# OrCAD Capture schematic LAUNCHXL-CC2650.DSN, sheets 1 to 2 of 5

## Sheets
1 5_Mech: size A3; title: LAUNCHXL-CC2650; rev: 1.3.0; company: Texas Instruments
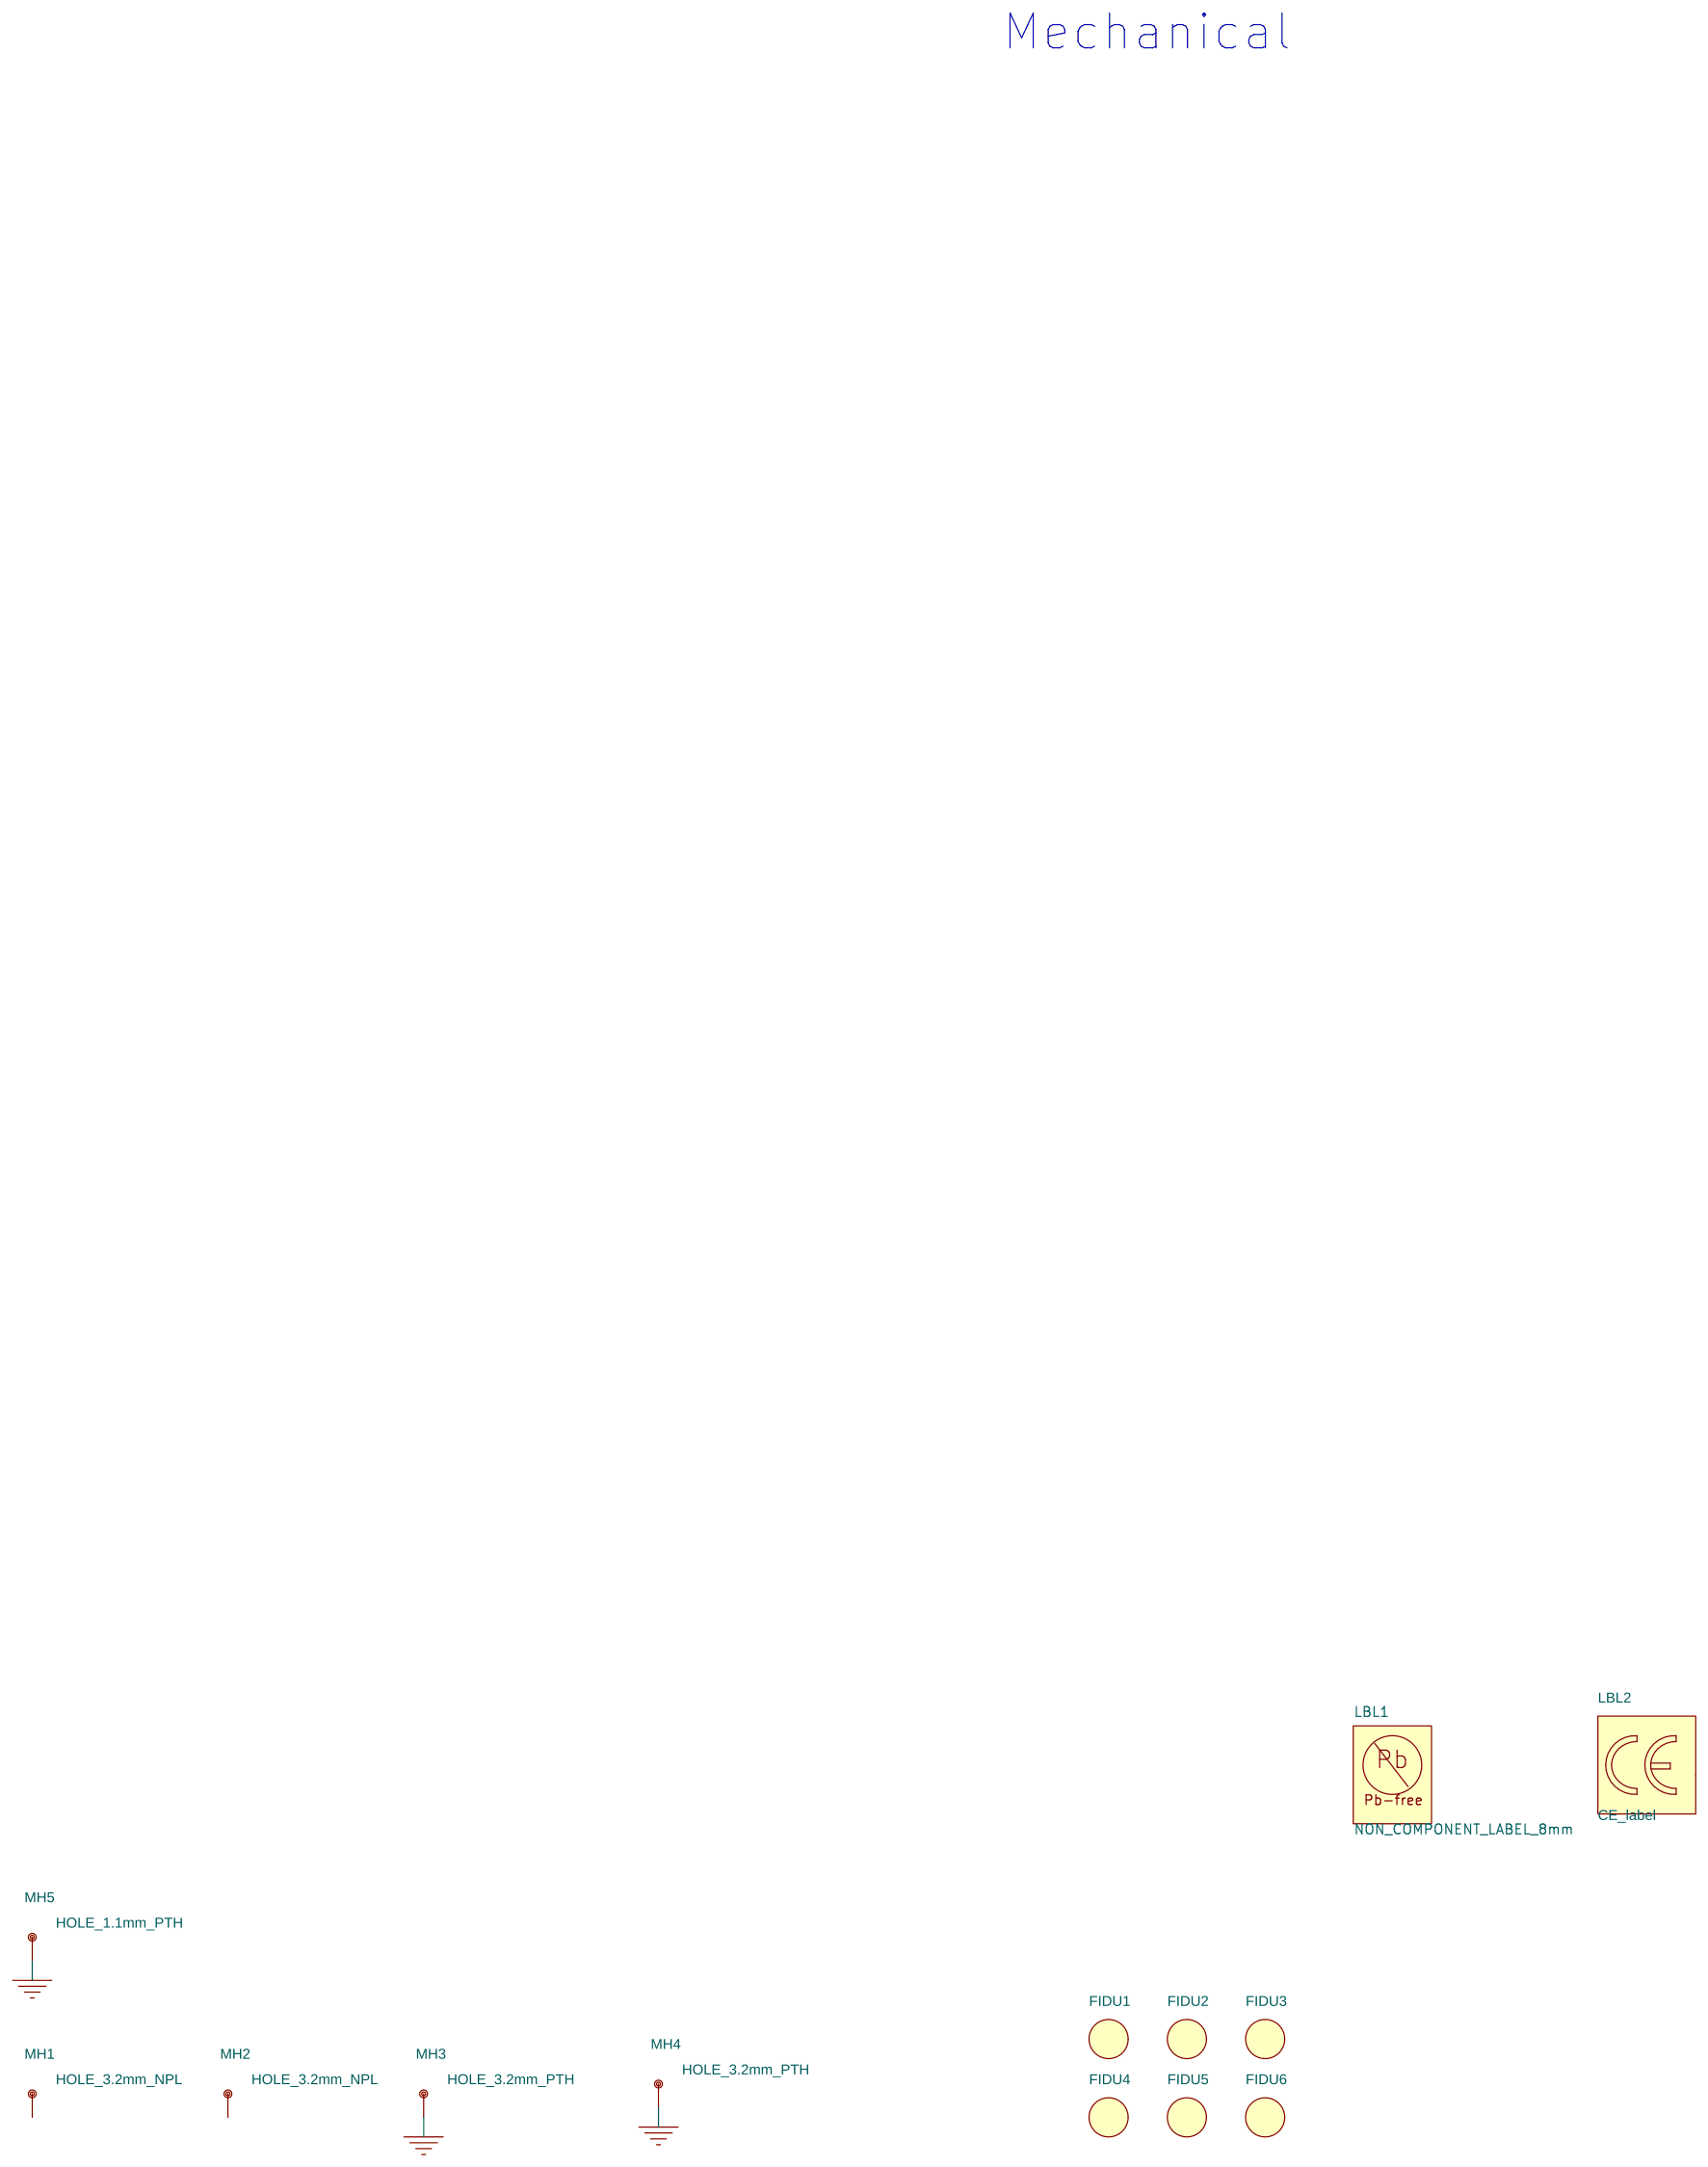
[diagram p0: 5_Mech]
2 3_Debugger Interface: size A3
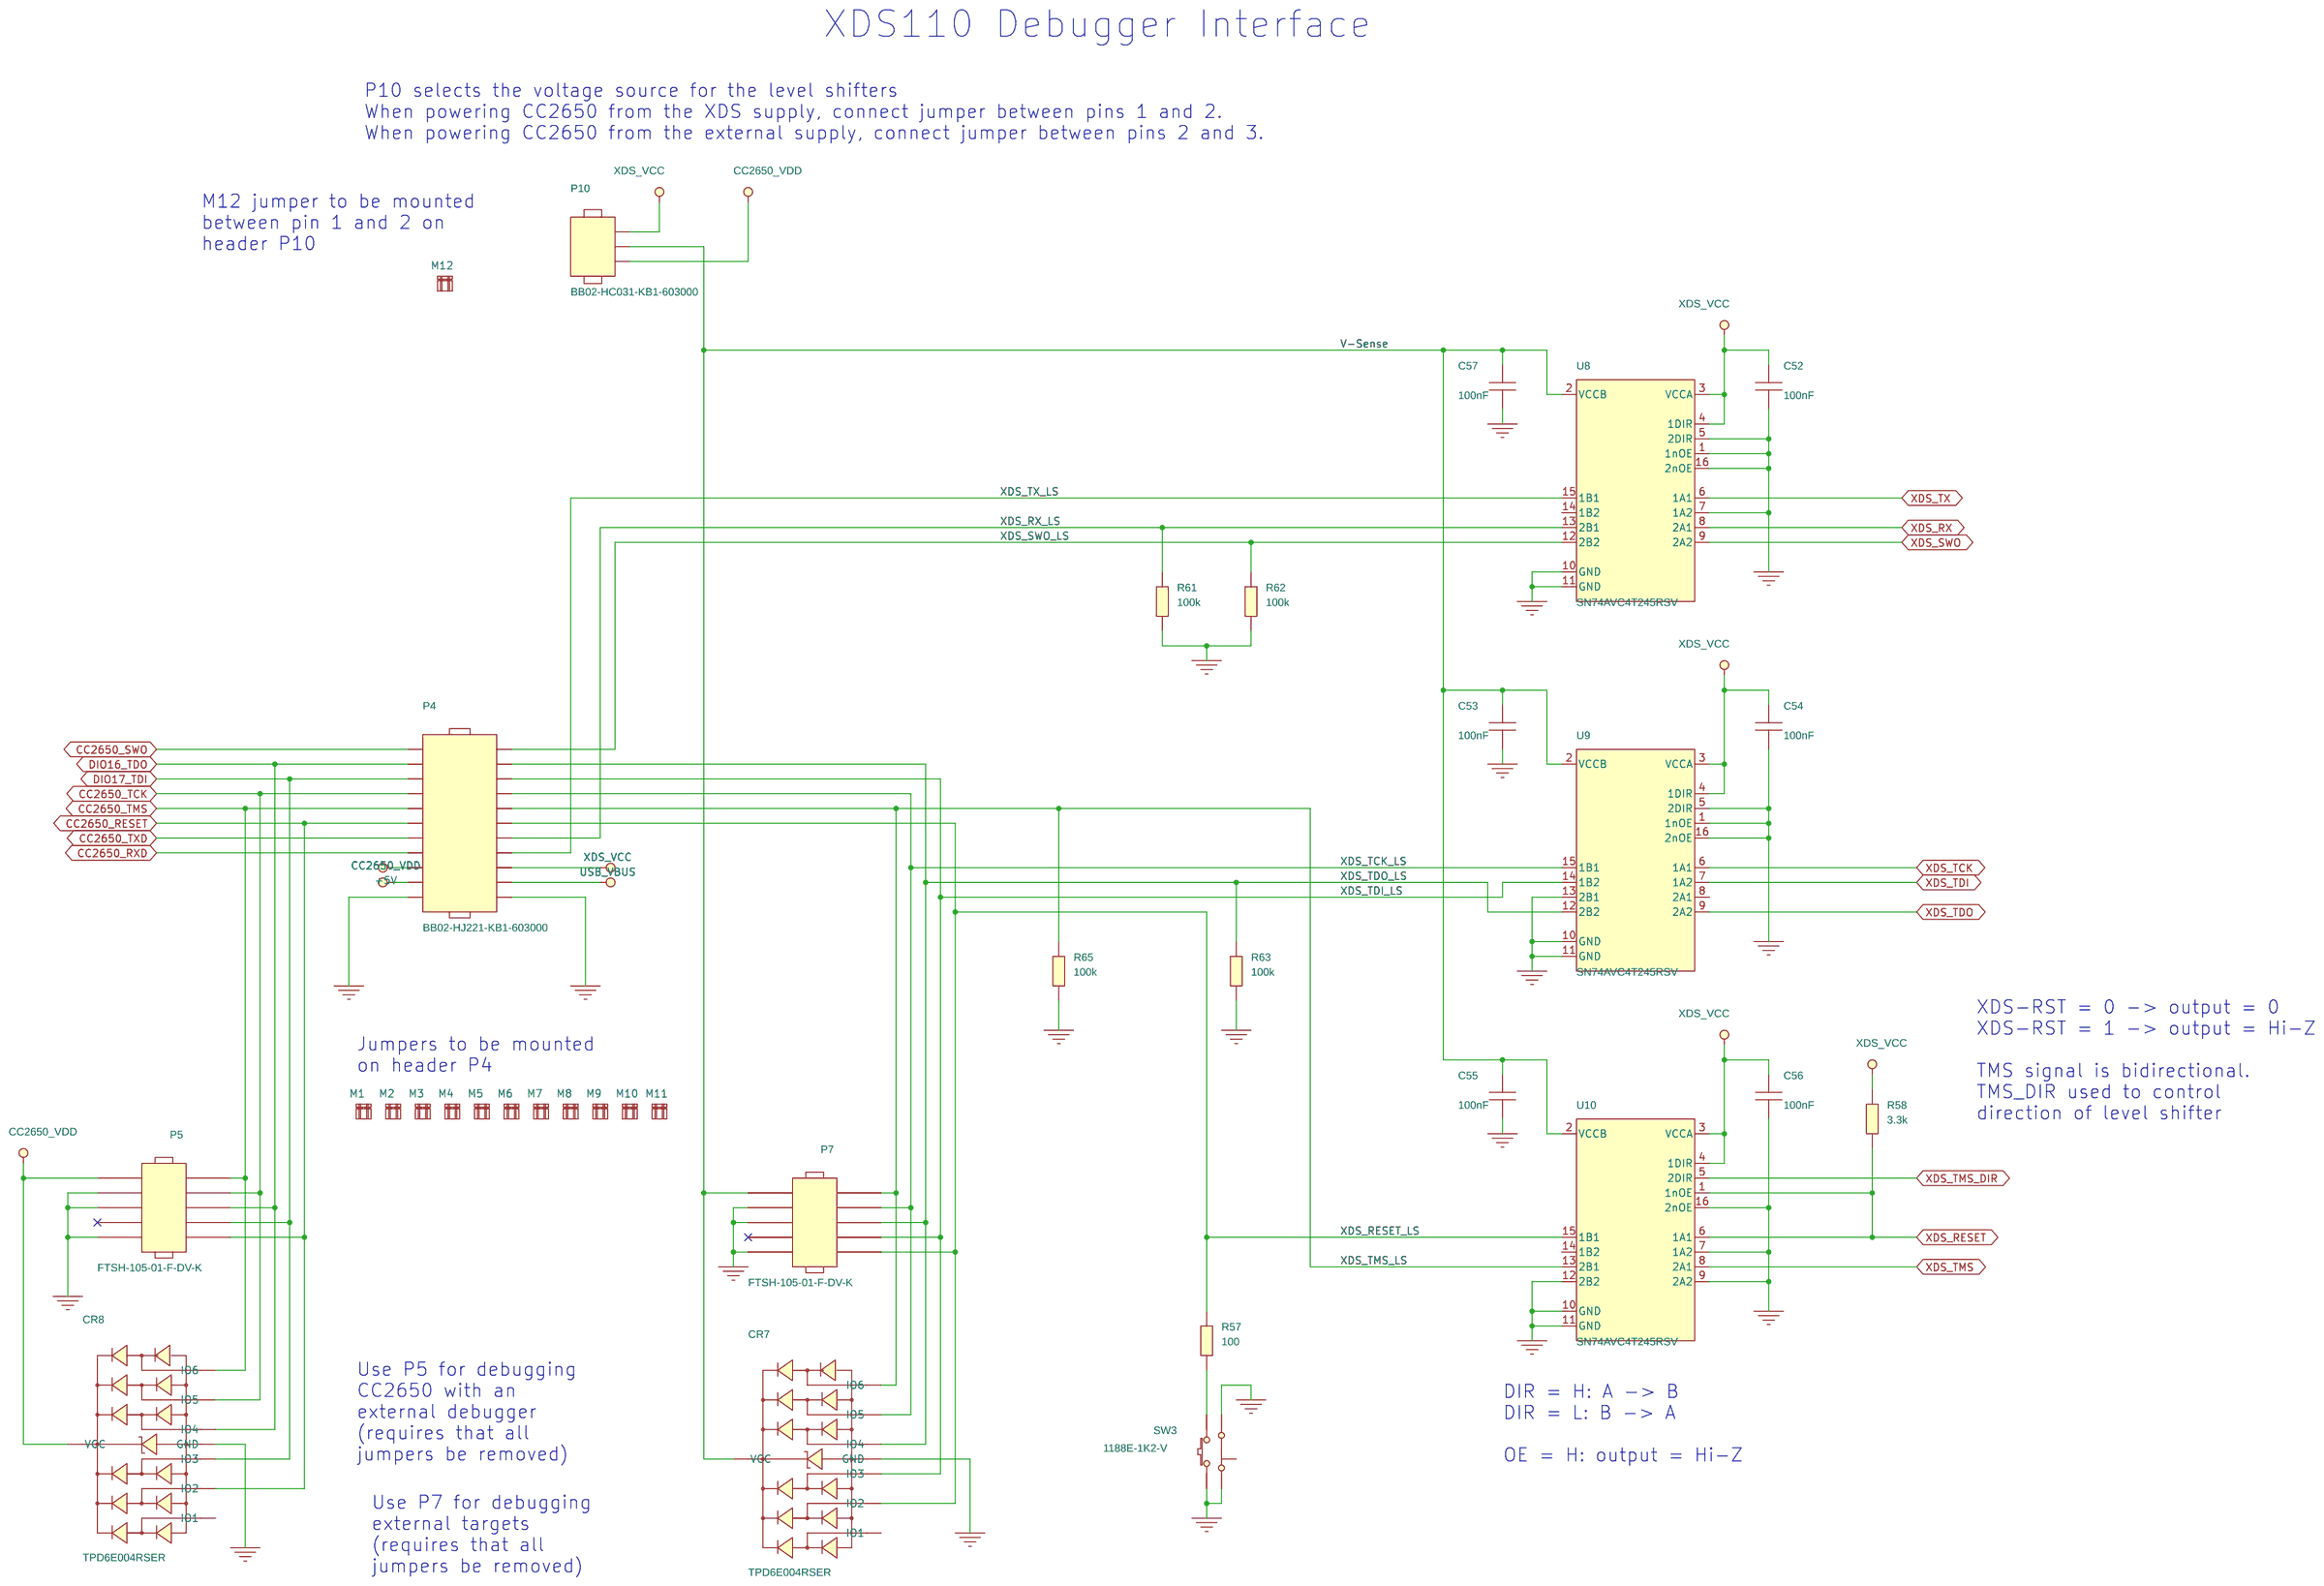
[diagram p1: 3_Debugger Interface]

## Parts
sheet 3_Debugger Interface
C52  100nF  [CAPC1005X60B2N]
C53  100nF  [CAPC1005X60B2N]
C54  100nF  [CAPC1005X60B2N]
C55  100nF  [CAPC1005X60B2N]
C56  100nF  [CAPC1005X60B2N]
C57  100nF  [CAPC1005X60B2N]
CR7  TPD6E004RSER  [QFN50P150X150X60-8N]
CR8  TPD6E004RSER  [QFN50P150X150X60-8N]
M1  SNT-100-BK-G
M2  SNT-100-BK-G
M3  SNT-100-BK-G
M4  SNT-100-BK-G
M5  SNT-100-BK-G
M6  SNT-100-BK-G
M7  SNT-100-BK-G
M8  SNT-100-BK-G
M9  SNT-100-BK-G
M10  SNT-100-BK-G
M11  SNT-100-BK-G
M12  SNT-100-BK-G
P4  BB02-HJ221-KB1-603000  [GRADCONN_BB02HJ221KB160300_A2B]
P5  FTSH-105-01-F-DV-K  [SAMTEC_FTSH-105-01-F-DV-K-10L]
P7  FTSH-105-01-F-DV-K  [SAMTEC_FTSH-105-01-F-DV-K-10L]
P10  BB02-HC031-KB1-603000  [GRADCONN_BB02HC031KB1603000_A2B]
R57  100  [RESC1005X40B2N]
R58  3.3k  [RESC1005X40B2N]
R61  100k  [RESC1005X40B2N]
R62  100k  [RESC1005X40B2N]
R63  100k  [RESC1005X40B2N]
R65  100k  [RESC1005X40B2N]
SW3  1188E-1K2-V  [SW_1188E1K2V_A2N]
U8  SN74AVC4T245RSV  [QFNFC40P180X260X55-16A2L]
U9  SN74AVC4T245RSV  [QFNFC40P180X260X55-16A2L]
U10  SN74AVC4T245RSV  [QFNFC40P180X260X55-16A2L]
sheet 5_Mech
FIDU1  FIDU_1.27mm  [FID127X142]
FIDU2  FIDU_1.27mm  [FID127X142]
FIDU3  FIDU_1.27mm  [FID127X142]
FIDU4  FIDU_1.27mm  [FID127X142]
FIDU5  FIDU_1.27mm  [FID127X142]
FIDU6  FIDU_1.27mm  [FID127X142]
LBL1  NON_COMPONENT_LABEL_8mm  [LABEL_PB-FREE_8MM_A2N]
LBL2  CE_label  [CE_label]
MH1  HOLE_3.2mm_NPL  [MTG320]
MH2  HOLE_3.2mm_NPL  [MTG320]
MH3  HOLE_3.2mm_PTH  [MTG320_380]
MH4  HOLE_3.2mm_PTH  [MTG320_380]
MH5  HOLE_1.1mm_PTH  [MTG110_170]

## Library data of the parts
C52-C57 = CAPACITOR: CAPACITOR, CERAMIC X7R, 100nF, 6.3V, -10%/+10%, -55DEGC/+125DEGC, 0402, SMD; AutoDoc File: https://notefied-dynamic-precision.com/DB/Apps/Desktop/Item/Object.aspx?id=113338; BU Name: TEXAS INSTRUMENTS NORWAY; Budget Currency: EUR; Budget Price: 0.007; Country of Origin: PHILIPPINES; Datasheet URL 1: http://psearch.murata.com/capacitor/product/GRM155R70J104KA01%23.pdf; Datasheet URL 2: http://search.murata.co.jp/Ceramy/image/img/w_hinm/L0005E.pdf; Definied Quality: INDUSTRIAL; Dielectric Type: X7R; Esd Level: N/A; Last Time Buy: N/A; Lead Time: 14; LifeCycle Status: ACTIVE; MPN: CAPACITOR_0402_100nF_X7R_M_+/-10%_10V; MPN Status: ACTIVE; MSL: N/A; MTBF: N/A; MTBF Standard: N/A; Manufacturer: MANUFACTURER SELECTION; Max Oper Temp: +125DEGC; Max Tol: +10%; Min Oper Temp: -55DEGC; Min Tol: -10%; Mounting Type: SMD; NOTE Status: PREFERRED; Old Footprint: CAPC1005X60N; PCB Package: 0402; Packing Size: 10000; Packing Type: TAPE_&_REEL; Part Number: 02-07610; Part Type: CAPACITOR\CERAMIC\0402\STANDARD; Revision: R000; RoHS Status: ROHS_COMPLIANT; Rtd Voltage: 6.3V; Vendor: MURATA; Vendor Part Number: GRM155R70J104KA01D; Vendor Part Status: NRND; WEIGHT: 0.0016g
CR7 CR8 = DIODE_TVS_TPD6E004_QFN8_V1_0: DIODE, PROTECTION, ESD, 7V, -40DEGC/+85DEGC, QFN8, SMD; ALT_SYMBOLS: QFN50P150X150X60-8L,QFN50P150X150X60-8M,QFN50P150X150X60-8AL; AutoDoc File: http://notefied-dynamic-precision.com/DB/Apps/Desktop/Item/Object.aspx?id=74721; Budget Currency: USD; Budget Price: 0.27; Datasheet URL 1: N/A; Datasheet URL 2: http://www.ti.com/lit/ds/symlink/tpd6e004.pdf; Definied Quality: INDUSTRIAL; Esd Level: HBM 15kV; FPLIST: QFN50P150X150X60-8N,QFN50P150X150X60-8AN,QFN50P150X150X60-8L,QFN50P150X150X60-8M,QFN50P150X150X60-8AL; Last Time Buy: N/A; Lead Time: 6; LifeCycle Status: MATURITY; MPN Status: ACTIVE; MSL: 1; MTBF: 9.9*10^8; MTBF Standard: MTTF,CL=60%,Tu=55,Ea=0.7,Tt=125; Manufacturer: TEXAS INSTRUMENTS; Max Oper Temp: +85DEGC; Min Oper Temp: -40DEGC; Mounting Type: SMD; NOTE Status: PREFERRED; Old Footprint: QFN50P150X150X60-8N,QFN50P150X150X60-8AN; PCB Package: QFN8; Packing Size: 3000; Packing Type: TAPE_&_REEL; Part Number: 14-05493; Part Type: DIODE\PROTECTION; Revision: R001; RoHS Status: ROHS_COMPLIANT; Rtd Voltage: 7V; WEIGHT: 0.0027g
M1-M12 = MECH_SHUNT_JUMPER: MECHANIC, SHUNT, CURRENT RATING 4.3A PER PIN, 2.54 X 5.08 X 6.1mm, BLACK; AutoDoc File: http://notefied-dynamic-precision.com/DB/Apps/Desktop/Item/Object.aspx?id=104092; Budget Currency: USD; Budget Price: 0.146; Datasheet URL 1: http://suddendocs.samtec.com/prints/snt-100-xx-x-x-mkt.pdf; Datasheet URL 2: http://suddendocs.samtec.com/catalog_english/snt.pdf; Definied Quality: INDUSTRIAL; Esd Level: N/A; Last Time Buy: N/A; Lead Time: 1; LifeCycle Status: ACTIVE; MPN Status: ACTIVE; MSL: N/A; MTBF: N/A; MTBF Standard: N/A; Manufacturer: SAMTEC; Max Oper Temp: +125DEGC; Min Oper Temp: -55DEGC; Mounting Type: NOT APPLY; NOTE Status: PREFERRED; Packing Size: 1; Packing Type: BULK; Part Number: 19-00498; Part Type: MECHANIC\SHUNT; Revision: R001; RoHS Status: ROHS_COMPLIANT; Rtd Current: 4.3A; WEIGHT: N/A
P4 = CONN_HEADER_2X11_P_S: CONNECTOR, HEADER, MALE, STRAIGHT, 2 ROWS, 22 PINS, PITCH 2.54mm, PTH; ALT_SYMBOLS: GRADCONN_BB02HJ221KB160300_A2C,GRADCONN_BB02HJ221KB160300_A2A; AutoDoc File: http://notefied-dynamic-precision.com/DB/Apps/Desktop/Item/Object.aspx?id=105022; Datasheet URL 1: http://www.gradconn.com/Files/Drawings/BB02-HJ.pdf; Datasheet URL 2: http://www.gradconn.com/Files/Specs/BTB-2.54mm-Header-specification.pdf; Definied Quality: INDUSTRIAL; MPN Status: ACTIVE; Manufacturer: GRADCONN; Max Oper Temp: +105DEGC; Min Oper Temp: -40DEGC; Mounting Type: PTH; NOTE Status: PREFERRED; No Of Pos: 22; No Of Rows: 2; Part Number: 06-05049; Part Type: CONNECTOR\HEADER; Pitch: 2.54mm; Revision: R001; RoHS Status: ROHS_COMPLIANT; Rtd Current: 3A; Rtd Voltage: 600VAC
P5 P7 = CONN_HEADER_2X5: CONNECTOR, HEADER, MALE, STRAIGHT, 10 PINS, 2 ROWS, PITCH 1.27mm, SMD; ALT_SYMBOLS: SAMTEC_FTSH-105-01-F-DV-K-10L,SAMTEC_FTSH-105-01-F-DV-K-10M; AutoDoc File: http://notefied-dynamic-precision.com/DB/Apps/Desktop/Item/Object.aspx?id=50836; Budget Currency: USD; Budget Price: 1.700; Datasheet URL 1: http://www.samtec.com/documents/webfiles/cpdf/FTSH-1XX-XX-XXX-DV-XXX-MKT.pdf; Datasheet URL 2: http://www.samtec.com/documents/webfiles/pdf/FTSH_SMT.PDF; FPLIST: SAMTEC_FTSH-105-01-F-DV-K-10N,SAMTEC_FTSH-105-01-F-DV-K-10L,SAMTEC_FTSH-105-01-F-DV-K-10M; Lead Time: 2; LifeCycle Status: MATURITY; MPN Status: ACTIVE; Manufacturer: SAMTEC; Max Oper Temp: +125DEGC; Min Oper Temp: -55DEGC; Mounting Type: SMD; NOTE Status: PREFERRED; No Of Pos: 10; No Of Rows: 2; Old Footprint: SAMTEC_FTSH-105-01-F-DV-K-10N,CONN_MALE_2X5; Packing Size: 92; Packing Type: TUBE; Part Number: 06-00166; Part Type: CONNECTOR\HEADER; Pitch: 1.27mm; Revision: R003; RoHS Status: ROHS_COMPLIANT; Rtd Current: 1.75A; WEIGHT: 0.65614g
P10 = CONN_HEADER_3_P_S: CONNECTOR, HEADER, MALE, STRAIGHT, 1 ROW, 3 PINS, PITCH 2.54mm, PTH; ALT_SYMBOLS: GRADCONN_BB02HC031KB1603000_A2C,GRADCONN_BB02HC031KB1603000_A2A; AutoDoc File: http://notefied-dynamic-precision.com/DB/Apps/Desktop/Item/Object.aspx?id=104636; Datasheet URL 1: http://www.gradconn.com/Files/Drawings/BB02-HC.pdf; Datasheet URL 2: http://www.gradconn.com/Files/Specs/BTB-2.54mm-Header-specification.pdf; MPN Status: ACTIVE; Manufacturer: GRADCONN; Max Oper Temp: +105DEGC; Min Oper Temp: -40DEGC; Mounting Type: PTH; NOTE Status: PREFERRED; No Of Pos: 3; No Of Rows: 1; Part Number: 06-05038; Part Type: CONNECTOR\HEADER; Pitch: 2.54mm; Revision: R001; RoHS Status: ROHS_COMPLIANT; Rtd Current: 3A; Rtd Voltage: 250V
R57 = RESISTOR: RESISTOR, THICK FILM, 100, -5%/+5%, 0.063W, 50V, -55DEGC/+155DEGC, 0402, SMD; AutoDoc File: https://notefied-dynamic-precision.com/DB/Apps/Desktop/Item/Object.aspx?id=113316; BU Name: TEXAS INSTRUMENTS NORWAY; Budget Currency: USD; Budget Price: 0.00244; Country of Origin: MISSING INFO; Datasheet URL 1: N/A; Datasheet URL 2: N/A; Definied Quality: INDUSTRIAL; Esd Level: N/A; Last Time Buy: N/A; Lead Time: N/A; LifeCycle Status: ACTIVE; MPN: RESISTOR_0402_100_+/-5%_50V_0.063W_M_+/-200ppm; MPN Status: ACTIVE; MSL: N/A; MTBF: N/A; MTBF Standard: N/A; Manufacturer: MANUFACTURER SELECTION; Max Oper Temp: +155DEGC; Max TC: +200PPM/DEGC; Max Tol: +5%; Min Oper Temp: -55DEGC; Min TC: -200PPM/DEGC; Min Tol: -5%; Mounting Type: SMD; NOTE Status: PREFERRED; Old Footprint: RESC1005X40N; PCB Package: 0402; Packing Size: 10000; Packing Type: TAPE_&_REEL; Part Number: 01-22343; Part Type: RESISTOR\0402\STANDARD; Resistor Type: THICK FILM; Revision: R000; RoHS Status: ROHS_COMPLIANT; Rtd Current: N/A; Rtd Power: 0.063W; Rtd Voltage: 50V; Vendor: MANUFACTURER SELECTION; Vendor Part Number: RESISTOR_0402_100_+/-5%_50V_0.063W_M_+/-200ppm; Vendor Part Status: ACTIVE; WEIGHT: N/A
R58 = RESISTOR: RESISTOR, THICK FILM, 3.3k, -5%/+5%, 0.063W, 50V, -55DEGC/+155DEGC, 0402, SMD; AutoDoc File: https://notefied-dynamic-precision.com/DB/Apps/Desktop/Item/Object.aspx?id=113324; BU Name: TEXAS INSTRUMENTS NORWAY; Budget Currency: USD; Budget Price: 0.00244; Country of Origin: MISSING INFO; Datasheet URL 1: N/A; Datasheet URL 2: N/A; Definied Quality: INDUSTRIAL; Esd Level: N/A; Last Time Buy: N/A; Lead Time: N/A; LifeCycle Status: ACTIVE; MPN: RESISTOR_0402_3.3k_+/-5%_50V_0.063W_M_+/-200ppm; MPN Status: ACTIVE; MSL: N/A; MTBF: N/A; MTBF Standard: N/A; Manufacturer: MANUFACTURER SELECTION; Max Oper Temp: +155DEGC; Max TC: +200PPM/DEGC; Max Tol: +5%; Min Oper Temp: -55DEGC; Min TC: -200PPM/DEGC; Min Tol: -5%; Mounting Type: SMD; NOTE Status: PREFERRED; Old Footprint: RESC1005X40N; PCB Package: 0402; Packing Size: 10000; Packing Type: TAPE_&_REEL; Part Number: 01-22351; Part Type: RESISTOR\0402\STANDARD; Resistor Type: THICK FILM; Revision: R000; RoHS Status: ROHS_COMPLIANT; Rtd Current: N/A; Rtd Power: 0.063W; Rtd Voltage: 50V; Vendor: MANUFACTURER SELECTION; Vendor Part Number: RESISTOR_0402_3.3k_+/-5%_50V_0.063W_M_+/-200ppm; Vendor Part Status: ACTIVE; WEIGHT: N/A
R61-R63 R65 = RESISTOR: RESISTOR, THICK FILM, 100k, -1%/+1%, 0.063W, 50V, -55DEGC/+155DEGC, 0402, SMD; AutoDoc File: https://notefied-dynamic-precision.com/DB/Apps/Desktop/Item/Object.aspx?id=113333; BU Name: TEXAS INSTRUMENTS NORWAY; Budget Currency: USD; Budget Price: 0.00244; Country of Origin: MISSING INFO; Datasheet URL 1: N/A; Datasheet URL 2: N/A; Definied Quality: INDUSTRIAL; Esd Level: N/A; Last Time Buy: N/A; Lead Time: N/A; LifeCycle Status: ACTIVE; MPN: RESISTOR_0402_100k_+/-1%_50V_0.063W_M_+/-100PPM; MPN Status: ACTIVE; MSL: N/A; MTBF: N/A; MTBF Standard: N/A; Manufacturer: MANUFACTURER SELECTION; Max Oper Temp: +155DEGC; Max TC: +100PPM/DEGC; Max Tol: +1%; Min Oper Temp: -55DEGC; Min TC: -100PPM/DEGC; Min Tol: -1%; Mounting Type: SMD; NOTE Status: PREFERRED; Old Footprint: RESC1005X40N; PCB Package: 0402; Packing Size: 10000; Packing Type: TAPE_&_REEL; Part Number: 01-22360; Part Type: RESISTOR\0402\PRECISION; Resistor Type: THICK FILM; Revision: R000; RoHS Status: ROHS_COMPLIANT; Rtd Current: N/A; Rtd Power: 0.063W; Rtd Voltage: 50V; Vendor: MANUFACTURER SELECTION; Vendor Part Number: RESISTOR_0402_100k_+/-1%_50V_0.063W_M_+/-100ppm; Vendor Part Status: ACTIVE; WEIGHT: N/A
SW3 = SWITCH_TACT_V2: SWITCH, TACT, 0.05A@250VAC, 0.05A@12VDC, 0.05A, 250V, SMD; ALT_SYMBOLS: SW_1188E1K2V_A2L,SW_1188E1K2V_A2M; AutoDoc File: http://notefied-dynamic-precision.com/DB/Apps/Desktop/Item/Object.aspx?id=104642; Datasheet URL 1: N/A; Datasheet URL 2: http://www.dip.com.tw/en/en-product-information/en-switch004; FPLIST: SW_1188E1K2V_A2N,SW_1188E1K2V_A2L,SW_1188E1K2V_A2M; MPN: 1188E-1K2-V-TR; MPN Status: ACTIVE; Manufacturer: DIPTRONICS; Max Oper Temp: +70DEGC; Min Oper Temp: -25DEGC; Mounting Type: SMD; NOTE Status: PREFERRED; Packing Size: 1500; Packing Type: TAPE_&_REEL; Part Number: 08-00293; Part Type: SWITCH\TACT; Revision: R001; RoHS Status: ROHS_COMPLIANT; Rtd Current: 0.05A; Rtd Voltage: 12V
U8-U10 = IC_XCVR_SN74AVC4T245_UQFN16_2: IC, DIGITAL, LOGIC, 4bit DUAL-SUPPLY BUS TRANSCEIVER 3 STATE OUTPUT, 1.2V TO 3.6V, UQFN16, SMD; ALT_SYMBOLS: QFNFC40P180X260X55-16A2L,QFNFC40P180X260X55-16A2M; AutoDoc File: http://notefied-dynamic-precision.com/DB/Apps/Desktop/Item/Object.aspx?id=95718; Budget Currency: USD; Budget Price: 0.39; Datasheet URL 1: http://www.ti.com/litv/pdf/mpqf205c; Datasheet URL 2: http://www.ti.com/lit/ds/symlink/sn74avc4t245.pdf; Definied Quality: INDUSTRIAL; FPLIST: QFNFC40P180X260X55-16A2N,QFNFC40P180X260X55-16A2L,QFNFC40P180X260X55-16A2M; Last Time Buy: N/A; Lead Time: 8; LifeCycle Status: ACTIVE; MPN: SN74AVC4T245RSVR; MPN Status: ACTIVE; MSL: 1; Manufacturer: TEXAS INSTRUMENTS; Max Oper Temp: +85DEGC; Min Oper Temp: -40DEGC; Mounting Type: SMD; NOTE Status: PREFERRED; Old Footprint: QFNFC40P180X260X55-16A2N; PCB Package: UQFN16; Packing Size: 3000; Packing Type: TAPE_&_REEL; Part Number: 18-29288; Part Type: IC\DIGITAL\LOGIC\TRANSCEIVER; Revision: R002; RoHS Status: ROHS_COMPLIANT; Rtd Voltage: 1.2V TO 3.6V; WEIGHT: 0.0062g
FIDU1-FIDU6 = FIDMARK: FIDUCIAL MARK, ROUND 1.27MM; Part Number: 19-00300; Part Type: NON_COMPONENT\FIDUCIAL
LBL1 = LABEL_Pb-free_V1: NON COMPONENT, LABEL, PB-FREE, 8mm; AutoDoc File: https://notefied-dynamic-precision.com/DB/Apps/Desktop/Item/Object.aspx?id=57438; BU Name: DYNAMIC PRECISION GDANSK; Part Number: 19-00159; Part Type: NON_COMPONENT\LABEL; Revision: R002
LBL2 = CE_LABEL: NON COMPONENT, LABEL, CE; AutoDoc File: https://notefied-dynamic-precision.com/DB/Apps/Desktop/Item/Object.aspx?id=87771; BU Name: DYNAMIC PRECISION GDANSK; Part Number: 19-00351; Part Type: NON_COMPONENT\LABEL; Revision: R001
MH1 MH2 = HOLE_NPL: NON COMPONENT, HOLE 3.2mm, NON PLATED HOLE; AutoDoc File: http://notefied-dynamic-precision.com/DB/Apps/Desktop/Item/Object.aspx?id=57308; FPLIST: MTG320,HOLE_80CIR126_32,; Old Footprint: MTG320,HOLE_80CIR126_32; Part Number: 19-00029; Part Type: NON_COMPONENT\HOLE\NON_PLATED; Revision: R001
MH3 MH4 = HOLE_PTH: NON COMPONENT, HOLE 3.2mm, PLATED HOLE; AutoDoc File: http://notefied-dynamic-precision.com/DB/Apps/Desktop/Item/Object.aspx?id=57362; FPLIST: MTG320_380,HOLE_150CIR126_32,; Old Footprint: MTG320_380,HOLE_150CIR126_32; Part Number: 19-00083; Part Type: NON_COMPONENT\HOLE\PLATED; Revision: R001
MH5 = HOLE_PTH: NON COMPONENT, HOLE 1.1mm, PLATED HOLE; AutoDoc File: http://notefied-dynamic-precision.com/DB/Apps/Desktop/Item/Object.aspx?id=57341; FPLIST: MTG110_170,; Part Number: 19-00062; Part Type: NON_COMPONENT\HOLE\PLATED; Revision: R001

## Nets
+5V: P4.20 ; also on sheet 4
GND: C52.2 C53.2 C54.2 C55.2 C56.2 C57.2 CR7.4(GND) CR8.4(GND) MH3.1 MH4.1 MH5.1 P4.21 P4.22 P5.3 P5.5 P5.9 P7.3 P7.5 P7.9 R61.1 R62.1 R63.1 R65.1 SW3.1 SW3.2 SW3.4 U8.1(1nOE) U8.5(2DIR) U8.7(1A2) U8.10(GND) U8.11(GND) U8.16(2nOE) U9.1(1nOE) U9.5(2DIR) U9.10(GND) U9.11(GND) U9.13(2B1) U9.16(2nOE) U10.7(1A2) U10.9(2A2) U10.10(GND) U10.11(GND) U10.12(2B2) U10.16(2nOE) ; also on sheet 3 4 5
CC2650_RESET: CR8.2(IO2) P4.12 P5.10 ; also on sheet 4 5
CC2650_RXD: P4.16 ; also on sheet 4
CC2650_SWO: P4.2 ; also on sheet 4
CC2650_TCK: CR8.6(IO5) P4.8 P5.4 ; also on sheet 4 5
CC2650_TMS: CR8.7(IO6) P4.10 P5.2 ; also on sheet 4 5
CC2650_TXD: P4.14 ; also on sheet 4
CC2650_VDD: CR8.8(VCC) P4.18 P5.1 P10.3 ; also on sheet 4 5
DIO16_TDO: CR8.5(IO4) P4.4 P5.6 ; also on sheet 4
DIO17_TDI: CR8.3(IO3) P4.6 P5.8 ; also on sheet 4
USB_VBUS: P4.19 ; also on sheet 3
V-Sense: C53.1 C55.1 C57.1 CR7.8(VCC) P7.1 P10.2 U8.2(VCCB) U9.2(VCCB) U10.2(VCCB)
XDS_RESET: R58.1 U10.1(1nOE) U10.6(1A1) ; also on sheet 3
XDS_RESET_LS: CR7.2(IO2) P4.11 P7.10 R57.2 U10.15(1B1)
XDS_RX: U8.8(2A1) ; also on sheet 3
XDS_RX_LS: P4.13 R61.2 U8.13(2B1)
XDS_SWO: U8.9(2A2) ; also on sheet 3
XDS_SWO_LS: P4.1 R62.2 U8.12(2B2)
XDS_TCK: U9.6(1A1) ; also on sheet 3
XDS_TCK_LS: CR7.6(IO5) P4.7 P7.4 U9.15(1B1)
XDS_TDI: U9.7(1A2) ; also on sheet 3
XDS_TDI_LS: CR7.3(IO3) P4.5 P7.8 U9.14(1B2)
XDS_TDO: U9.9(2A2) ; also on sheet 3
XDS_TDO_LS: CR7.5(IO4) P4.3 P7.6 R63.2 U9.12(2B2)
XDS_TMS: U10.8(2A1) ; also on sheet 3
XDS_TMS_DIR: U10.5(2DIR) ; also on sheet 3
XDS_TMS_LS: CR7.7(IO6) P4.9 P7.2 R65.2 U10.13(2B1)
XDS_TX: U8.6(1A1) ; also on sheet 3
XDS_TX_LS: P4.15 U8.15(1B1)
XDS_VCC: C52.1 C54.1 C56.1 P4.17 P10.1 R58.2 U8.3(VCCA) U8.4(1DIR) U9.3(VCCA) U9.4(1DIR) U10.3(VCCA) U10.4(1DIR) ; also on sheet 3
N1384129: R57.1 SW3.3

Not connected (* = marked no-connect by the designer): CR7 1(IO1); CR8 1(IO1); FIDU1 1; FIDU2 1; FIDU3 1; FIDU4 1; FIDU5 1; FIDU6 1; LBL2 1; MH1 1; MH2 1; P5 7*; P7 7*; U8 14(1B2); U9 8(2A1); U10 14(1B2)

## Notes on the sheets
sheet 1
- Mechanical
sheet 2
- XDS110 Debugger Interface
- P10 selects the voltage source for the level shifters
  When powering CC2650 from the XDS supply, connect jumper between pins 1 and 2.
  When powering CC2650 from the external supply, connect jumper between pins 2 and 3.
- M12 jumper to be mounted
  between pin 1 and 2 on
  header P10
- XDS-RST = 0 -> output = 0
  XDS-RST = 1 -> output = Hi-Z
  TMS signal is bidirectional.
  TMS_DIR used to control
  direction of level shifter
- Jumpers to be mounted
  on header P4
- Use P5 for debugging
  CC2650 with an
  external debugger
  (requires that all
  jumpers be removed)
- DIR = H: A -> B
  DIR = L: B -> A
  OE = H: output = Hi-Z
- Use P7 for debugging
  external targets
  (requires that all
  jumpers be removed)
